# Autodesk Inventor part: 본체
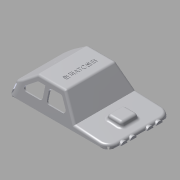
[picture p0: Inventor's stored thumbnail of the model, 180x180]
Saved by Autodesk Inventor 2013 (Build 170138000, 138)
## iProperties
Created: 2015-05
Part Number: 본체
Material: ABS 플라스틱
Document SubType Name: Modeling
Designer: WINDOWS7
Density: 1.06 g/cm^3
Mass: 31.6438 g
Surface Area: 310.19 cm^2
Volume: 29.8527 cm^3
Author: WINDOWS7
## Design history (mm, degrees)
sketch "스케치2"
  geometry: L1 (-58.819, 3.58)-(63.181, 3.58); L2 (-58.819, 3.58)-(-63.995, 22.898); L3 (-58.819, 3.58)-(-38.819, 3.58); L4 (-58.819, 3.58)-(-58.819, 23); L5 (-58.819, 3.58)-(-58.623, 7.814); L6 (-58.623, 7.814)-(-16.819, 10.005); L7 (-16.819, 3.58)-(-16.819, 52); L8 (-16.819, 10.005)-(-34.026, 34.58); L9 (-16.819, 10.005)-(13.181, 10.005); L10 (-16.819, 10.005)-(0.388, 34.58); L11 (33.181, 3.58)-(33.181, 49.685); L12 (0.388, 34.58)-(33.181, 34.58); L13 (63.181, 3.58)-(60.334, 14.205); L14 (63.181, 3.58)-(74.181, 3.58); L15 (60.334, 14.205)-(33.181, 34.58); 2 further points
  constraints: 30 end point, 4 horizontal, 4 point on line, 3 equal length, 3 perpendicular, 2 symmetric about line, 1 parallel
  dimensions: "d3" = 122 distance of L1.end L1.start; "d7" = 20 distance of L1.start L2.end; "d8" = 105 deg angle of L3 L2; "d10" = 3 deg angle of L1 L6; "d11" = 58.92148 distance from line of L5 point (0, 0); "d16" = 42 distance from line of L1.start L7; "d17" = 30 distance of L6.end L8.end; "d18" = 125 deg angle of L9 L8; "d19" = 30 distance from line of L1.end L11; "d20" = 11 distance of L1.end L13.end; "d21" = 105 deg angle of L14 L13 (derived); "d23" = 128 deg angle of L6 L10; "d24" = 4.27949 distance from line of point (-53.643, 22.898) L5; "d73" = 31 distance between parallel lines of L1 L12; "d76" = 3.5798 vertical distance of L1.start point (0, 0)
extrude "돌출1" new body sketch "스케치2" distance "d25" = 76; taper "d26" = 0 deg
sketch "스케치3"
  geometry: L1 (0, 0)-(122, 0) reference; L2 (122, 0)-(122, 76) reference; L3 (0, 76)-(122, 76) reference; L4 (0, 0)-(0, 76) reference; L5 (1, 75)-(121, 75); L6 (121, 75)-(121, 1); L7 (121, 1)-(1, 1); L8 (1, 1)-(1, 75); 1 further point
  constraints: 8 end point, 2 parallel, 1 horizontal, 1 perpendicular
  dimensions: "d28" = 120 distance between parallel lines of L6 L8; "d30" = 74 distance between parallel lines of L7 L5; "d31" = 1 distance between parallel lines of L1 L7; "d32" = 1 distance between parallel lines of L4 L8
extrude "돌출2" cut sketch "스케치3" distance "d33" = 1; taper "d34" = 0 deg
node "작업 평면1"
sketch "스케치5"
  geometry: L1 (62.913, 4.58)-(-58.773, 4.58) reference; L2 (-58.623, 7.814)-(-58.773, 4.58) reference; L3 (-16.819, 10.005)-(-58.623, 7.814) reference; L4 (0.388, 34.58)-(-16.819, 10.005) reference; L5 (33.181, 34.58)-(0.388, 34.58) reference; L6 (60.334, 14.205)-(33.181, 34.58) reference; L7 (62.913, 4.58)-(60.334, 14.205) reference; L8 (-47.623, 8.391)-(-45.774, 14.439); L9 (-45.774, 14.439)-(-29.746, 14.439); L10 (-29.746, 14.439)-(-27.623, 9.439); L11 (-15.901, 8.051)-(-56.709, 5.912) reference; 1 further point
  constraints: 6 end point, 2 point on line, 1 parallel
  dimensions: "d35" = 70 deg angle of L3 L8; "d36" = 70 deg angle of L3 L10; "d37" = 11 horizontal distance of L2.start L8.start; "d38" = 20 horizontal distance of L10.end L8.start; "d39" = 5 distance from line of L10.end L9
extrude "돌출3" join sketch "스케치5" stored distance "d40" = 20; taper "d41" = 0 deg
node "작업 평면2"
sketch "스케치7"
  geometry: L1 (0, 9.625)-(0, 30) reference; L2 (0, 30)-(76, 30) reference; L3 (76, 9.625)-(76, 30) reference; L4 (0, 9.625)-(76, 9.625) reference; L5 (76, 0)-(0, 0) reference; L6 (0, 0)-(0, 9.625) reference; L7 (0, 9.625)-(76, 9.625) reference; L8 (76, 0)-(76, 9.625) reference; L9 (76, 0)-(67.962, 30); L10 (0, 0)-(8.038, 30); L11 (0, 0)-(0, 30); L12 (8.038, 30)-(0, 30); L13 (67.962, 30)-(76, 30); L14 (76, 0)-(76, 30); 1 further point
  constraints: 14 end point, 2 point on line, 1 collinear
  dimensions: "d44" = 105 deg angle of L5 L9; "d45" = 105 deg angle of L5 L10
extrude "돌출4" cut sketch "스케치7" distance "d46" = 122; taper "d47" = 0 deg
feature "쉘2" dims "d48" = 2
sketch "스케치8"
  geometry: L1 (79.732, -5.617)-(62.525, -31.058) reference; L2 (62.525, -31.058)-(29.732, -31.058) reference; L3 (70.015, -11.058)-(59.87, -26.058); L4 (45.015, -11.058)-(45.015, -26.058); L5 (29.732, -31.058)-(2.579, -9.965); L6 (31.446, -26.058)-(12.137, -11.058); L7 (12.137, -11.058)-(40.137, -11.058); L8 (40.137, -11.058)-(40.137, -26.058); L9 (40.137, -26.058)-(31.446, -26.058); L10 (70.015, -11.058)-(45.015, -11.058); L11 (45.015, -26.058)-(59.87, -26.058); 1 further point
  constraints: 18 end point, 3 horizontal alignment, 3 parallel, 2 perpendicular, 2 vertical alignment
  dimensions: "d59" = 5 distance between parallel lines of L1 L3; "d65" = 25 distance from line of L3.start L4; "d67" = 5 distance between parallel lines of L5 L6; "d68" = 28 distance of L6.end L7.end; "d69" = 5 distance between parallel lines of L11 L2; "d70" = 15 distance between parallel lines of L10 L11; "d71" = 5 distance between parallel lines of L2 L9; "d72" = 15 distance between parallel lines of L7 L9
extrude "돌출5" cut sketch "스케치8" distance "d74" = 5; taper "d75" = 0 deg
node "작업 평면3"
sketch "스케치9"
  geometry: L1 (-3.238, 0.867)-(-3.238, 75.133) reference; L2 (0.955, 38)-(-91.897, 38); L3 (0.955, 75)-(0.955, 1) reference; L4 (0.955, 75)-(-0.044, 75) reference; L5 (-0.044, 75)-(-0.044, 1) reference; L6 (0.955, 1)-(-0.044, 1) reference; L7 (0, 13.116)-(0, 20.884); L8 (0, 24.116)-(0, 31.884); L9 (0, 44.116)-(0, 51.884); L10 (0, 55.116)-(0, 62.884); A1 r 4 centre (0.955, 28) between (0, 31.884) and (0, 24.116); A2 r 4 centre (0.955, 17) between (0, 20.884) and (0, 13.116); A3 r 4 centre (0.955, 48) between (0, 51.884) and (0, 44.116); A4 r 4 centre (0.955, 59) between (0, 62.884) and (0, 55.116); 3 further points
  constraints: 10 end point, 8 point on circle, 4 centre point, 4 point on line, 2 vertical, 1 collinear, 1 midpoint, 1 parallel, 1 perpendicular, 9 other
  dimensions: "d79" = 8 diameter of A1; "d80" = 8 diameter of A2; "d85" = 11 distance of A4.centre A3.centre; "d86" = 11 distance of A1.centre A2.centre; "d87" = 10 distance of L2.start A3.centre; "d88" = 10 distance of L2.start A1.centre; "d89" = 4 radius of A3; "d90" = 4 radius of A4
extrude "돌출6" join sketch "스케치9" distance "d91" = 2; taper "d92" = 0 deg
sketch "스케치11"
  geometry: L1 (120, 74)-(0, 74) reference; L2 (120.732, 75)-(120.732, -1) reference; L3 (57.819, -6)-(57.819, 86); L4 (148, 37)-(-11, 37); C1 r 3 at (97.819, 37); C2 r 3 at (17.819, 37); C3 r 3 at (57.819, 15); C4 r 3 at (57.819, 59); 2 further points
  constraints: 6 point on line, 4 centre point, 4 end point, 2 perpendicular, 1 midpoint
  dimensions: "d97" = 6 diameter of C1; "d99" = 40 distance from line of L3 C1.centre; "d100" = 40 distance from line of L3 C2.centre; "d101" = 6 diameter of C2; "d102" = 6 diameter of C3; "d103" = 6 diameter of C4; "d104" = 22 distance from line of L4 C3.centre; "d105" = 22 distance from line of L4 C4.centre
extrude "돌출8" join sketch "스케치11" distance "d106" = 10; taper "d107" = 0 deg
extrude "돌출9" join sketch "스케치11" distance "d108" = 24; taper "d109" = 0 deg
node "작업 평면5"
sketch "스케치12"
  geometry: L1 (3, 0)-(-3, 0) reference; L2 (-2.072, 24)-(-2.072, 24) reference; L3 (-2.072, 24)-(-2.072, 24) reference; L4 (3, 0)-(3, 24) reference; L5 (-3, 0)-(-3, 22.674) reference; L6 (3, 24)-(-2.072, 24) reference; L7 (62.181, 0)-(-57.819, 0) reference; L8 (-3, 2)-(-5, 2); L9 (3, 2)-(5, 2); L10 (5, 2)-(8.522, 24); L11 (8.522, 24)-(3, 24); L12 (1.429, 29)-(-15.74, 4.479) reference; L13 (-5, 2)-(-7.673, 16); L14 (-7.673, 16)-(-3, 16); L15 (0, 0)-(0, 0); L16 (0, 0)-(0, 14); 1 further point
  constraints: 16 end point, 5 point on line, 3 perpendicular, 2 midpoint, 2 parallel, 1 collinear
  dimensions: "d114" = 5 horizontal distance of L15.start L8.end; "d116" = 5 horizontal distance of L15.start L9.end
extrude "돌출10" join sketch "스케치12" stored distance "d117" = 4; taper "d118" = 0 deg
node "작업 평면6"
sketch "스케치13"
  geometry: L1 (-3, 2)-(-4, 2); L2 (-4, 2)-(-5.076, 6.303); L3 (3, 2)-(4, 2); L4 (4, 2)-(6.951, 8.859); L5 (3, 0)-(-3, 0) reference; L6 (3, 8.859)-(-3, 8.859) reference; L7 (3, 0)-(3, 8.859) reference; L8 (-3, 0)-(-3, 8.859) reference; L9 (3, 8.859)-(6.951, 8.859); L10 (-6.12, 2.887)-(-4.294, 8.859) reference; L11 (-5.076, 6.303)-(-3, 6.303); L12 (0, 0)-(0, 8.859); L13 (83, 0)-(77, 0) reference; L14 (79.177, 24)-(79.177, 24) reference; L15 (79.177, 24)-(79.177, 24) reference; L16 (77, 0)-(77, 24) reference; L17 (83, 0)-(83, 21.132) reference; L18 (98.581, 9.44)-(72.514, 29) reference; L19 (77, 2)-(75, 2); L20 (75, 2)-(70, 24); L21 (70, 24)-(77, 24); L22 (83, 2)-(85, 2); L23 (85, 2)-(88, 18); L24 (88, 18)-(83, 18); L25 (80, 0)-(80, 14.557); L26 (-3, 6.303)-(-3, 2); L27 (83, 18)-(83, 2); L28 (77, 24)-(77, 2); 4 further points
  constraints: 34 end point, 8 point on line, 5 perpendicular, 4 collinear, 3 midpoint, 2 horizontal, 2 vertical alignment, 1 horizontal alignment, 1 parallel, 2 other
  dimensions: "d119" = 4 horizontal distance of L12.start L1.end; "d120" = 4 horizontal distance of L12.start L3.end; "d121" = 4.30315 distance between parallel lines of L1 L11; "d124" = 5 distance from line of L25 L22.end; "d125" = 5 distance from line of L25 L19.end; "d126" = 16 distance between parallel lines of L22 L24
  node "투영된 루프7"
  node "투영된 루프8"
extrude "돌출11" join sketch "스케치13" stored distance "d127" = 4; taper "d128" = 0 deg
extrude "돌출12" join sketch "스케치13" stored distance "d129" = 4; taper "d130" = 0 deg
extrude "돌출13" join sketch "스케치13" stored distance "d131" = 4; taper "d132" = 0 deg
node "작업 평면7"
sketch "스케치14"
  geometry: L1 (3, 0)-(-3, 0) reference; L2 (-2.072, 24)-(-2.072, 24) reference; L3 (-2.072, 24)-(-2.072, 24) reference; L4 (3, 0)-(3, 24) reference; L5 (-3, 0)-(-3, 22.674) reference; L6 (62.181, 0)-(-57.819, 0) reference; L7 (3, 24)-(-2.072, 24) reference; L8 (-3, 2)-(-5, 2); L9 (-5, 2)-(-7, 16); L10 (-7, 16)-(-3, 16); L11 (3, 2)-(5, 2); L12 (5, 2)-(10, 24); L13 (10, 24)-(3, 24); L14 (3, 24)-(3, 2); L15 (-3, 16)-(-3, 2); L16 (0, 0)-(0, 13.594); 2 further points
  constraints: 18 end point, 5 point on line, 4 parallel, 2 collinear, 1 midpoint, 1 perpendicular
  dimensions: "d133" = 5 distance from line of L16 L11.end; "d135" = 5 distance from line of L16 L8.end; "d136" = 14 distance between parallel lines of L8 L10; "d137" = 22 distance between parallel lines of L11 L13
extrude "돌출14" join sketch "스케치14" stored distance "d138" = 4; taper "d139" = 0 deg
fillet "모깎기1" dims "d140" = 12
fillet "모깎기2" dims "d141" = 3
fillet "모깎기3" dims "d142" = 3
fillet "모깎기4" dims "d143" = 3
fillet "모깎기5" dims "d144" = 3
sketch "스케치15"
  geometry: L1 (0, 0)-(0, 55.319) reference; L2 (30.231, 55.319)-(30.231, 0) reference; L3 (-30.732, 54.068)-(-30.732, 1.251) reference; L4 (19.268, 8.241)-(19.268, 47.078); L5 (16.422, 27.66)-(22.114, 27.66); L6 (0, 27.66)-(30.231, 27.66); 4 further points
  constraints: 6 end point, 4 midpoint, 1 point on line, 1 other
  dimensions: "d145" = 50 distance from line of point (19.268, 27.66) L3
extrude "돌출15" join sketch "스케치15" distance "d146" = 0.5; taper "d147" = 0 deg
node "솔리드1"
mirror "대칭1"
node "투영된 루프1"
node "투영된 루프3"
node "투영된 루프4"
node "투영된 루프5"
node "투영된 루프6"
node "투영된 루프9"
other parameters: "d60" = 5, "d61" = 15, "d81" = 8, "d82" = 8
